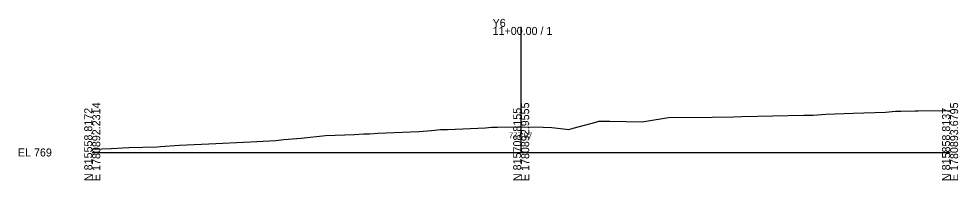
# Model space of a CAD drawing. Extents: x -26 to 1603, y -10 to 6024.
# Drawn here: x -25.7 to 302.8, y 990.3 to 1046.7 of the extents above; entities that cross this region are included whole.
import ezdxf

# ---------------------------------------------------------------- set-up
doc = ezdxf.new("R2010")
doc.units = 0
for name, color, linetype in [('Exist Cross Section Cell', 7, 'Continuous'), ('Exist XS Center Line Elevation Label', 7, 'Continuous'), ('Exist XS Ground Line', 7, 'Continuous')]:
    doc.layers.add(name, color=color, linetype=linetype)

msp = doc.modelspace()

# ---------------------------------------------------------------- linework, layer by layer
at = {"layer": 'Exist Cross Section Cell'}
for p, q in [((150, 1000), (150, 1043.89)), ((0, 1000), (150, 1000)), ((150, 1000), (300, 1000))]:
    msp.add_line(p, q, dxfattribs=at)
at = {"layer": 'Exist XS Ground Line'}
for p, q in [((193.7, 1010.92), (201.52, 1012.23)), ((201.52, 1012.23), (216.79, 1012.38)), ((216.79, 1012.38), (224.24, 1012.5)), ((224.24, 1012.5), (227.14, 1012.54)), ((227.14, 1012.54), (248.83, 1012.99)), ((248.83, 1012.99), (252.1, 1013.1)), ((252.1, 1013.1), (256.59, 1013.36)), ((256.59, 1013.36), (266.06, 1013.69)), ((266.06, 1013.69), (277.43, 1014.12)), ((277.43, 1014.12), (280.9, 1014.39)), ((280.9, 1014.39), (282.75, 1014.43)), ((282.75, 1014.43), (287.83, 1014.52)), ((287.83, 1014.52), (288.88, 1014.55)), ((288.88, 1014.55), (300, 1014.63)), ((124.27, 1008), (137.53, 1008.63)), ((137.53, 1008.63), (139.65, 1008.79)), ((139.65, 1008.79), (141.68, 1008.82)), ((141.68, 1008.82), (150.29, 1008.98)), ((150.29, 1008.98), (157.64, 1008.82)), ((157.64, 1008.82), (160.75, 1008.76)), ((160.75, 1008.76), (164.78, 1008.26)), ((168.21, 1008.46), (176.13, 1010.63)), ((176.13, 1010.63), (177.2, 1010.99)), ((177.2, 1010.99), (181.05, 1011)), ((181.05, 1011), (186.77, 1010.83)), ((186.77, 1010.83), (192.08, 1010.72)), ((192.08, 1010.72), (193.7, 1010.92)), ((73.09, 1005.03), (81.58, 1005.95)), ((81.58, 1005.95), (91.75, 1006.31)), ((91.75, 1006.31), (94.85, 1006.49)), ((94.85, 1006.49), (96.93, 1006.56)), ((96.93, 1006.56), (99.82, 1006.7)), ((99.82, 1006.7), (114.32, 1007.39)), ((114.32, 1007.39), (118.66, 1007.67)), ((118.66, 1007.67), (121.73, 1007.98)), ((121.73, 1007.98), (124.27, 1008)), ((164.78, 1008.26), (166.71, 1008.02)), ((166.71, 1008.02), (168.21, 1008.46)), ((22.68, 1001.97), (23.9, 1002.05)), ((23.9, 1002.05), (30.53, 1002.59)), ((30.53, 1002.59), (40.76, 1003.04)), ((40.76, 1003.04), (55.29, 1003.73)), ((55.29, 1003.73), (64.21, 1004.17)), ((64.21, 1004.17), (67.05, 1004.52)), ((67.05, 1004.52), (73.09, 1005.03)), ((0, 1001.19), (6.64, 1001.42)), ((6.64, 1001.42), (12.85, 1001.7)), ((12.85, 1001.7), (22.68, 1001.97))]:
    msp.add_line(p, q, dxfattribs=at)

# ---------------------------------------------------------------- texts
at = {"layer": 'Exist Cross Section Cell'}
for s, p in [('Y6', (140, 1043.89)), ('11+00.00 / 1', (140, 1041.09)), ('EL 769', (-26, 998.6))]:
    msp.add_text(s, height=2.8, dxfattribs=at).set_placement(p)
for s, p in [('N 815558.8172', (0, 990)), ('E 1780892.2314', (2.8, 990)), ('N 815708.8155', (150, 990)), ('E 1780892.9555', (152.8, 990)), ('N 815858.8137', (300, 990)), ('E 1780893.6795', (302.8, 990))]:
    msp.add_text(s, height=2.8, rotation=90, dxfattribs=at).set_placement(p)
at = {"layer": 'Exist XS Center Line Elevation Label'}
msp.add_text('777.97', height=2, dxfattribs=at).set_placement((145.7, 1004.97))

doc.saveas('drawing.dxf')
